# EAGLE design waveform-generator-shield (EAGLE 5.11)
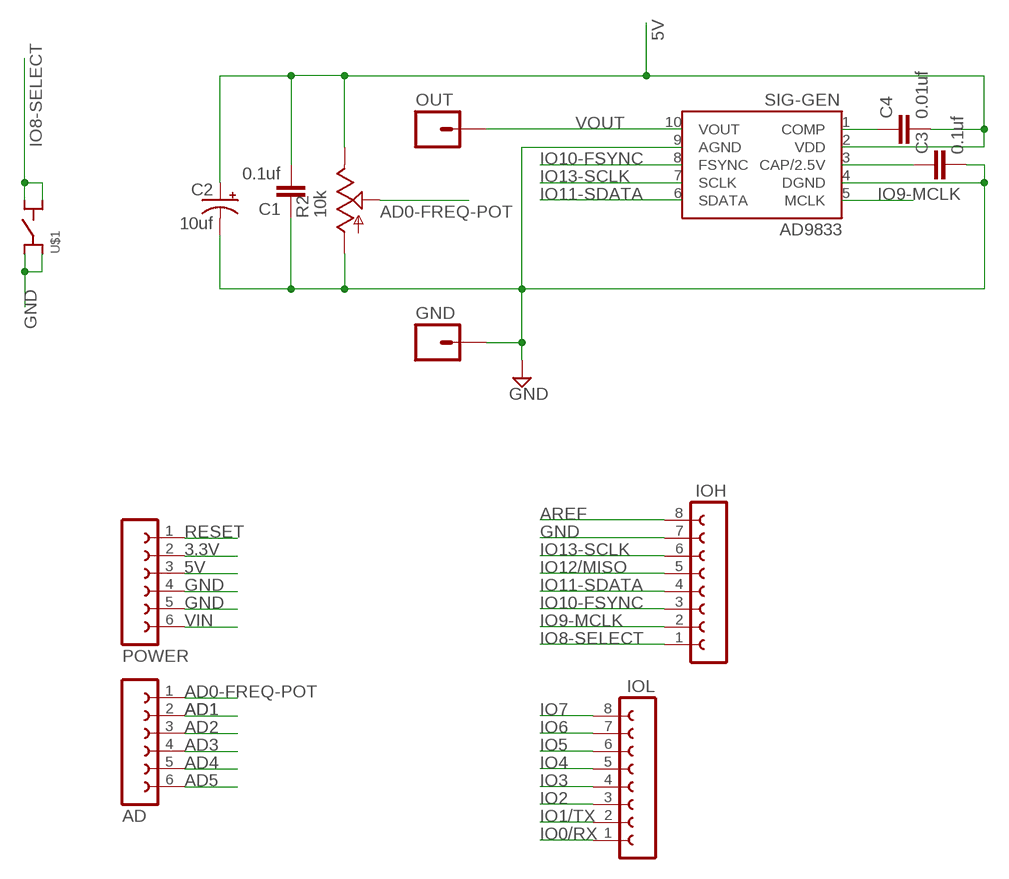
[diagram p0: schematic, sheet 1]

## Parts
AD  FE06-1  [FE06]
C1  0.1uf  C-EUC1206  [C1206]
C2  10uf  CPOL-USE2-5  [E2-5]
C3  0.1uf  C-EUC1206  [C1206]
C4  0.01uf  C-EU050-024X044  [C050-024X044]
GND  M01PTH_LONGPAD  [1X01_LONGPAD]
IOH  FE08-1  [FE08]
IOL  FE08-1  [FE08]
OUT  M01PTH_LONGPAD  [1X01_LONGPAD]
POWER  FE06-1  [FE06]
R2  10k  POT-TRIM-PARALLAX  [POT-TRIM-PARALLAX]
SIG-GEN  AD9833  [10MSOP]
U$1  SFE-PUSHBUTTON-SWITCH  [SFE-PUSHBUTTON-SWITCH]

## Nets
3.3V: POWER.2
5V: C1.2 C2.+ C4.2 POWER.3 R2.3(E) SIG-GEN.2(VDD)
AD0-FREQ-POT: AD.1 R2.2(S)
AD1: AD.2
AD2: AD.3
AD3: AD.4
AD4: AD.5
AD5: AD.6
AREF: IOH.8
GND: C1.1 C2.- C3.2 GND.1 IOH.7 POWER.4 POWER.5 R2.1(A) SIG-GEN.4(DGND) SIG-GEN.9(AGND) U$1.C@1(C) U$1.C@2(C)
IO0/RX: IOL.1
IO1/TX: IOL.2
IO2: IOL.3
IO3: IOL.4
IO4: IOL.5
IO5: IOL.6
IO6: IOL.7
IO7: IOL.8
IO8-SELECT: IOH.1 U$1.O@1(O) U$1.O@2(O)
IO9-MCLK: IOH.2 SIG-GEN.5(MCLK)
IO10-FSYNC: IOH.3 SIG-GEN.8(FSYNC)
IO11-SDATA: IOH.4 SIG-GEN.6(SDATA)
IO12/MISO: IOH.5
IO13-SCLK: IOH.6 SIG-GEN.7(SCLK)
N$6: C3.1 SIG-GEN.3(CAP/2.5V)
N$8: C4.1 SIG-GEN.1(COMP)
RESET: POWER.1
VIN: POWER.6
VOUT: OUT.1 SIG-GEN.10(VOUT)

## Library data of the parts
AD POWER = con-lsta:FE06-1: FEMALE HEADER; OC_FARNELL: unknown; OC_NEWARK: unknown
C1 C3 C4 = rcl:C-EU: CAPACITOR, European symbol
C2 = rcl:CPOL-US: POLARIZED CAPACITOR, American symbol
GND OUT = SparkFun2011-02-20:M01: Header 1
IOH IOL = con-lsta:FE08-1: FEMALE HEADER; OC_FARNELL: unknown; OC_NEWARK: unknown
R2 = trl:POT-TRIM-PARALLAX: POTENTIOMETER
SIG-GEN = trl:AD9833
U$1 = trl:SFE-PUSHBUTTON-SWITCH

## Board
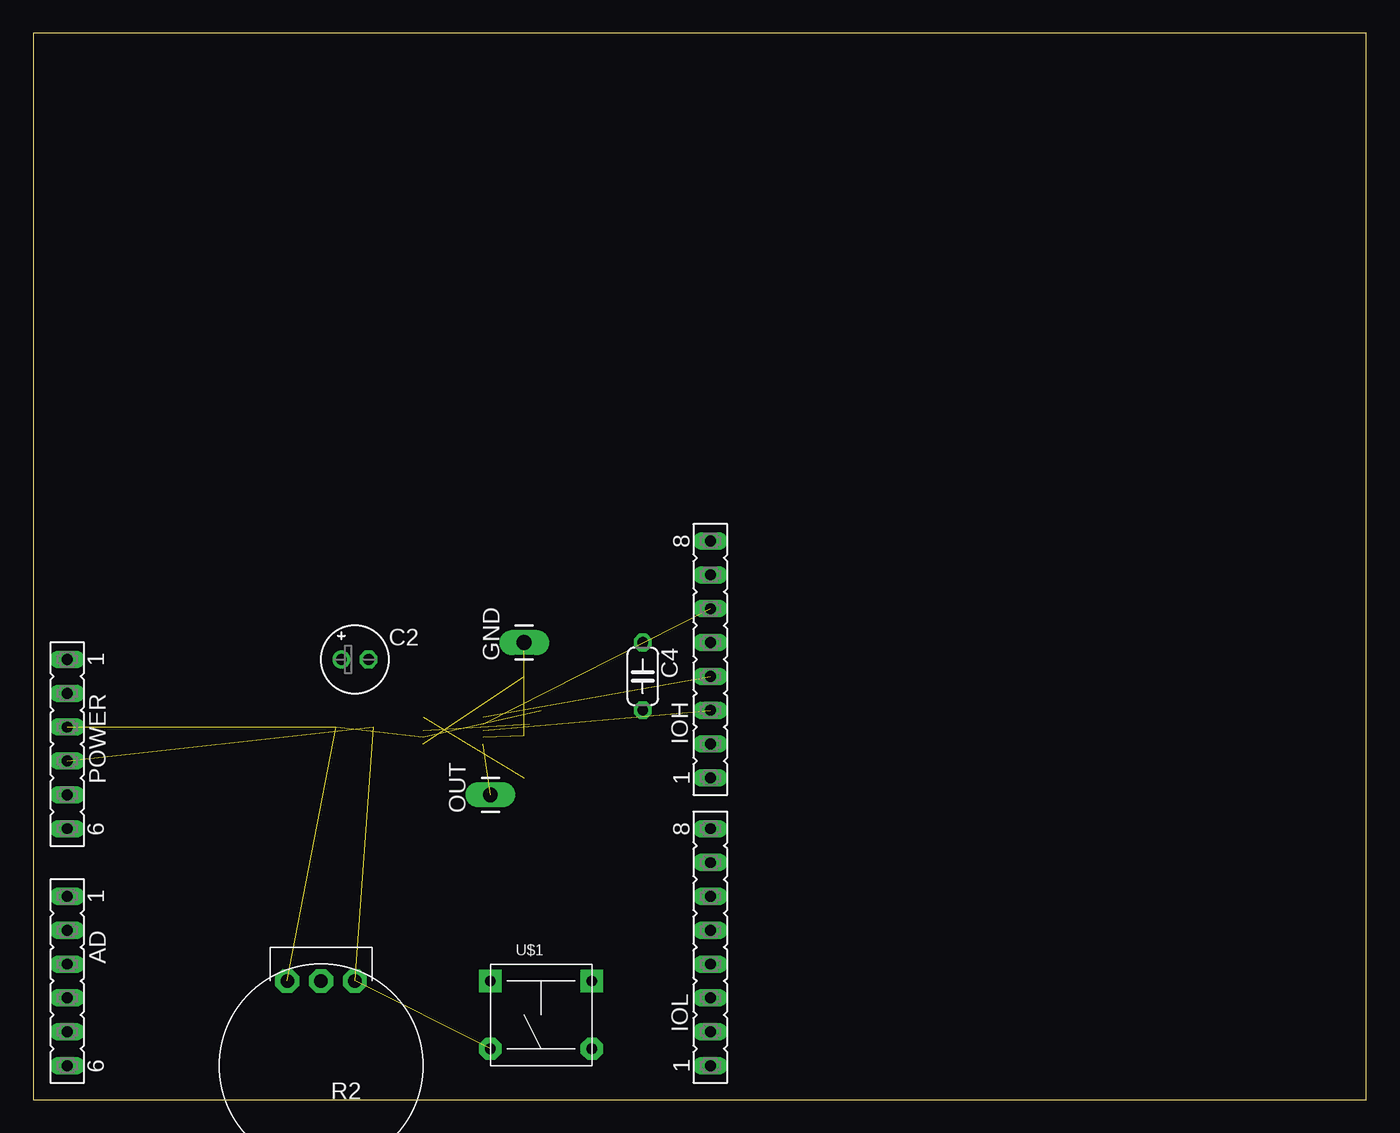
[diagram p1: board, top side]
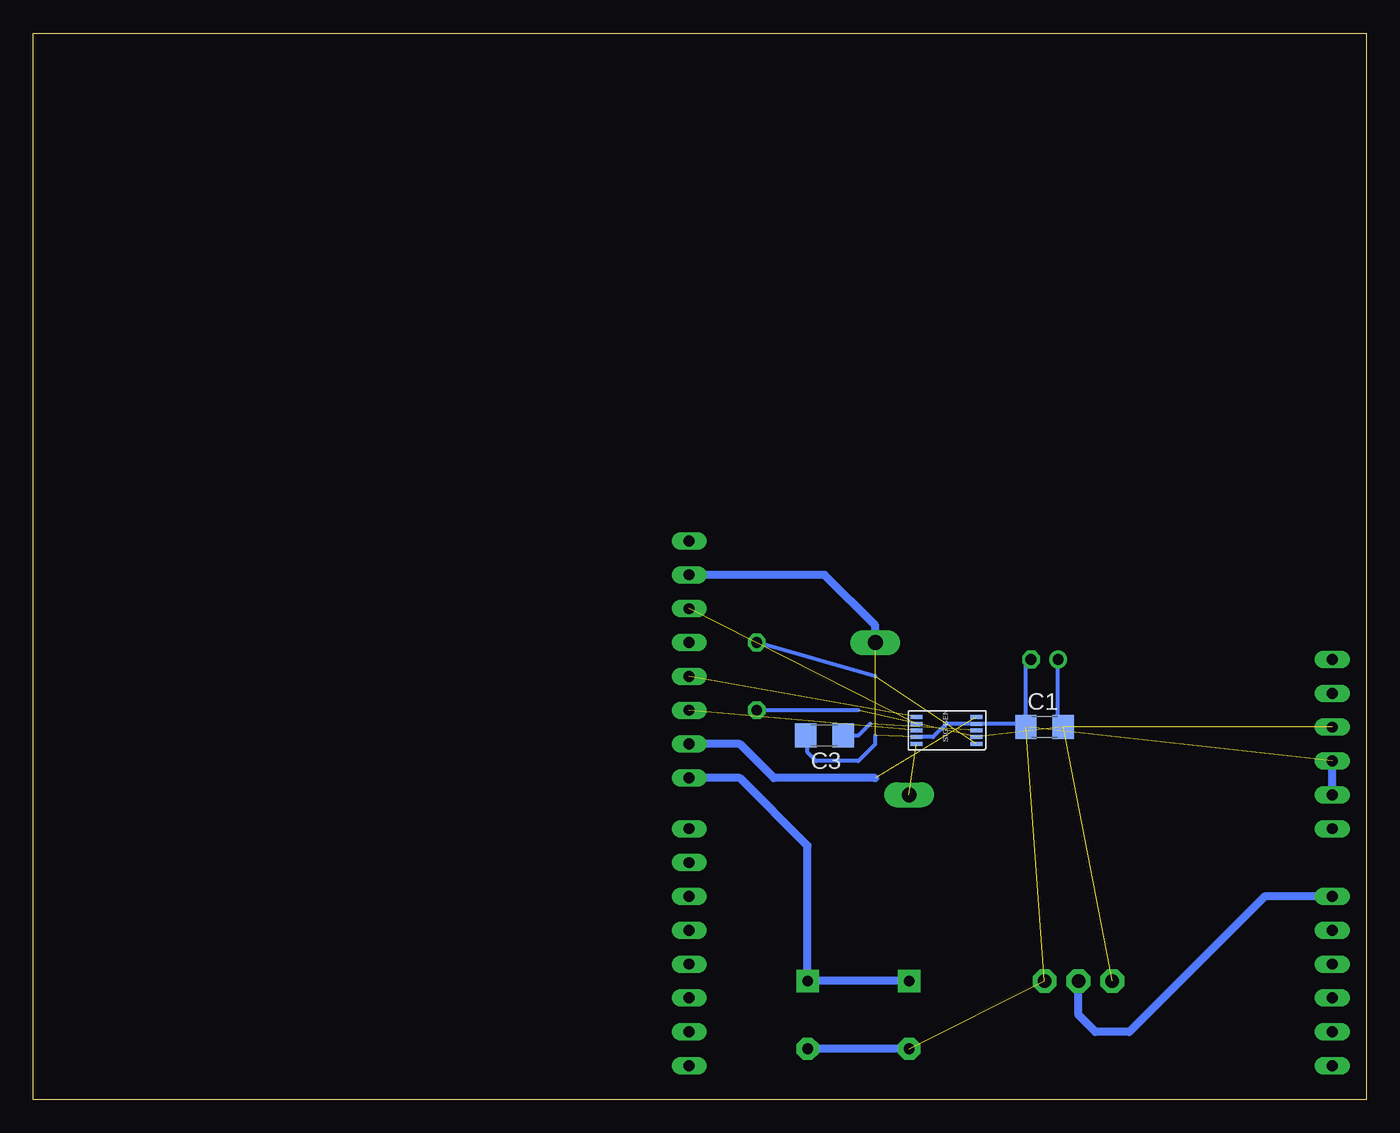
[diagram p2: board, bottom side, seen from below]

Size 100 x 80 mm. Coordinates in mm from the lower left corner, seen from the top.
Outline: 0,0 100,0 100,80 0,80 0,0
Copper layers (1*16): Top 0.035mm / dielectric 1.5mm / Bottom 0.035mm
Design rules "default": minimum track width 10mil, minimum drill 24mil, track to track 8mil, track to pad 8mil, pad to pad 8mil, via to via 8mil, smd to smd 8mil, copper to edge 40mil, drill to drill 8mil, minimum pad ring 10mil, minimum via ring 8mil, stop-mask expansion 4mil, vias tented up to drill 0mil, thermal gap 10mil

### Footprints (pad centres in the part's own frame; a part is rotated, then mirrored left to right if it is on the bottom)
FE06 = drill 0.813 long: 1 -6.35,0; 2 -3.81,0; 3 -1.27,0; 4 1.27,0; 5 3.81,0; 6 6.35,0
C1206 = smd 1.6 x 1.8: 1 -1.4,0; 2 1.4,0
E2-5 = drill 0.813 pad 1.27 round: + -1.016,0 | drill 0.813 pad 1.27 octagon: - 1.016,0
C050-024X044 = drill 0.813 octagon: 1 -2.54,0; 2 2.54,0
1X01_LONGPAD = drill 1.118 pad 1.88 long: 1 0,0
FE08 = drill 0.813 long: 1 -8.89,0; 2 -6.35,0; 3 -3.81,0; 4 -1.27,0; 5 1.27,0; 6 3.81,0; 7 6.35,0; 8 8.89,0
POT-TRIM-PARALLAX = drill 1.016 pad 1.778 octagon: 1 -2.54,-3.81; 2 0,-3.81; 3 2.54,-3.81
10MSOP = smd 0.3 x 0.9: 1 -1.25,-5.05; 2 -0.75,-5.05; 3 -0.25,-5.05; 4 0.25,-5.05; 5 0.75,-5.05; 6 0.75,-0.55; 7 0.25,-0.55; 8 -0.25,-0.55; 9 -0.75,-0.55; 10 -1.25,-0.55
SFE-PUSHBUTTON-SWITCH = drill 0.8 pad 1.676 octagon: C@1 -3.81,-2.54; C@2 3.81,-2.54 | drill 0.8 pad 1.676 square: O@1 -3.81,2.54; O@2 3.81,2.54

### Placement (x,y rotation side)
AD  2.54,8.89 270 top
C1  24.13,27.94 0 bottom
C2  24.13,33.02 0 top
C3  40.64,27.3 180 bottom
C4  45.72,31.75 270 top
GND  36.83,34.29 90 top
IOH  50.8,33.02 90 top
IOL  50.8,11.43 90 top
OUT  34.29,22.86 90 top
POWER  2.54,26.67 270 top
R2  21.59,5.08 180 top
SIG-GEN  34.29,27.94 90 bottom
U$1  38.1,6.35 0 top

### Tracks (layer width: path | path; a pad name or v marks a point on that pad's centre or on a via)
5V  (4 unrouted)
  Bottom 0.305: 38.1,29.21 C4.2 | C2.+ 23.11,28.32 C1.2
AD0-FREQ-POT
  Bottom 0.61: R2.2 21.59,6.35 20.32,5.08 17.78,5.08 7.62,15.24 AD.1
GND  (5 unrouted)
  Bottom 0.305: 36.83,27.3 36.83,26.67 38.1,25.4 41.27,25.4 41.91,26.04 41.91,27.18 C3.2 | C2.- 25.53,32.64 C1.1 25.78,28.19 SIG-GEN.4 31.5,28.19 32.5,27.19 SIG-GEN.9
  Bottom 0.61: U$1.C@1 U$1.C@2 | IOH.7 40.64,39.37 36.83,35.56 GND.1 36.83,33.66 | POWER.5 POWER.4
IO8-SELECT
  Bottom 0.61: IOH.1 46.99,24.13 41.91,19.05 U$1.O@2 U$1.O@1
IO9-MCLK  (1 unrouted)
  Bottom 0.61: 36.83,24.13 44.45,24.13 46.99,26.67 IOH.2
IO10-FSYNC  (1 unrouted)
IO11-SDATA  (1 unrouted)
IO13-SCLK  (1 unrouted)
N$6  (1 unrouted)
  Bottom 0.305: 37.22,28.19 38.1,27.3 C3.1
N$8  (1 unrouted)
  Bottom 0.305: 36.83,31.75 C4.1
VOUT  (1 unrouted)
